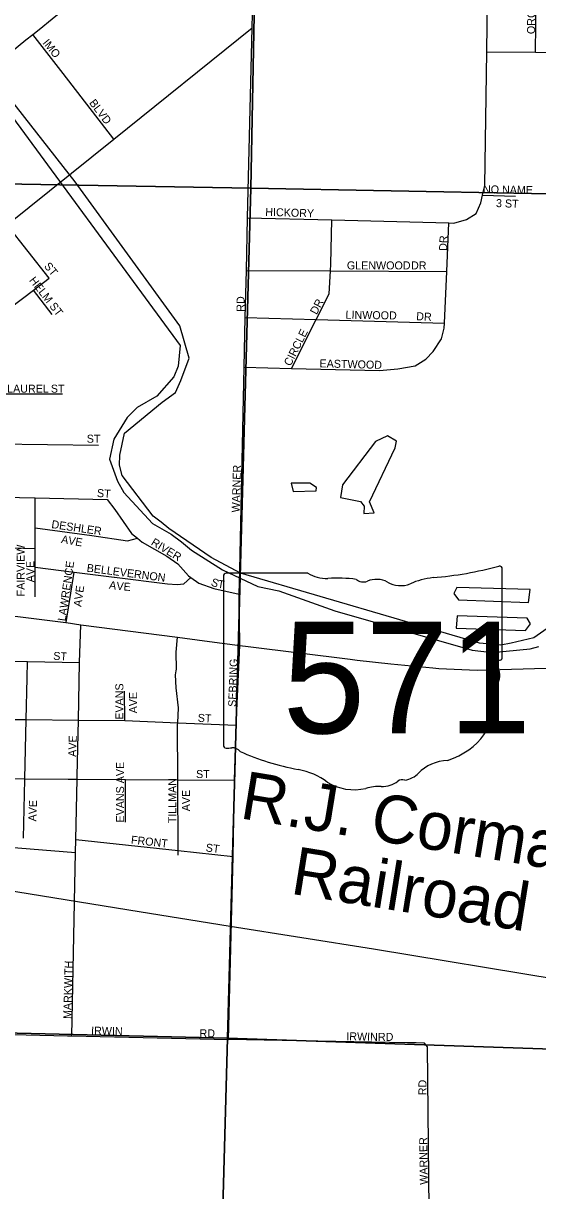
# Model space of a CAD drawing. Extents: x -784 to 1375, y -225 to 440.
# Drawn here: x 308.9 to 321.44, y 339.88 to 368.36 of the extents above; entities that cross this region are included whole.
import ezdxf

# ---------------------------------------------------------------- set-up
doc = ezdxf.new("R2010")
doc.units = 0
for name, color, linetype in [('GM_X_City_Street', 7, 'Continuous'), ('GM_X_City_Street_Text', 7, 'Continuous'), ('GM_X_County_Road', 7, 'Continuous'), ('GM_X_Major_River', 7, 'Continuous'), ('GM_X_Minor_Lake', 7, 'Continuous'), ('GM_X_Rail_Line', 7, 'Continuous'), ('GM_X_Rail_Line_Text', 7, 'Continuous'), ('GM_X_Section', 7, 'Continuous'), ('GM_X_State_Location', 7, 'Continuous'), ('GM_X_State_Route', 7, 'Continuous'), ('GM_X_State_Shield', 7, 'Continuous')]:
    doc.layers.add(name, color=color, linetype=linetype)

msp = doc.modelspace()

# ---------------------------------------------------------------- linework, layer by layer
at = {"layer": 'GM_X_City_Street'}
for points in [[(314.181, 355.025), (314.287, 359.97), (314.314, 361.184), (314.34, 362.327), (314.37, 363.611), (314.482, 368.251), (314.548, 370.985)], [(314.37, 363.611), (316.423, 363.56), (319.28, 363.488), (319.398, 363.485), (319.707, 363.569), (319.94, 363.718), (320.059, 363.98), (320.099, 364.162), (320.152, 364.4), (320.207, 367.666), (320.241, 370.994)], [(320.207, 367.666), (321.394, 367.658), (322.642, 367.65), (323.176, 367.646), (323.509, 367.729), (323.735, 367.91), (323.843, 368.102), (323.878, 370.999)], [(321.394, 367.658), (321.428, 370.996)], [(308.429, 363.378), (308.434, 363.382), (308.511, 363.444), (311.105, 365.533), (314.482, 368.251)], [(309.874, 367.13), (309.135, 368.088)], [(311.105, 365.533), (309.874, 367.13), (309.874, 367.13)], [(320.099, 364.162), (320.905, 364.14)], [(309.533, 362.144), (308.511, 363.444), (308.491, 363.47)], [(314.287, 359.97), (315.437, 359.941), (317.587, 359.885), (318.037, 359.933), (318.456, 360.006), (318.72, 360.162), (318.899, 360.351), (319.098, 360.658), (319.162, 360.923), (319.168, 361.04), (319.226, 362.307), (319.28, 363.488)], [(315.437, 359.941), (316.043, 361.133), (316.362, 361.76), (316.393, 362.319), (316.402, 362.479), (316.423, 363.56)], [(314.34, 362.327), (316.393, 362.319), (319.226, 362.307)], [(304.642, 358.327), (305.871, 359.317), (306.248, 359.621), (307.622, 360.677), (308.584, 361.415), (309.147, 361.848), (309.533, 362.144)], [(309.606, 361.257), (309.147, 361.848)], [(314.314, 361.184), (316.043, 361.133), (319.168, 361.04)], [(307.97, 359.317), (308.068, 359.317), (309.859, 359.316)], [(308.237, 358.1), (310.733, 358.066)], [(308.014, 356.811), (308.048, 356.81), (309.187, 356.785), (310.946, 356.745)], [(309.189, 355.978), (309.189, 356.048), (309.187, 356.785)], [(310.946, 356.745), (311.129, 356.498), (311.334, 356.203), (311.54, 355.916), (311.685, 355.796), (311.802, 355.699), (312.399, 355.356), (312.669, 355.17), (312.93, 354.882), (312.987, 354.842), (313.185, 354.704), (313.543, 354.57), (314.168, 354.429)], [(309.189, 356.048), (310.572, 355.86), (311.441, 355.731), (311.685, 355.796)], [(309.193, 354.364), (309.191, 355.093), (309.19, 355.548), (309.189, 355.978), (309.189, 355.978)], [(304.627, 355.657), (305.96, 355.625), (308.037, 355.576), (309.19, 355.548)], [(309.191, 355.093), (310.139, 354.972), (311.119, 354.847)], [(309.947, 353.744), (310.139, 354.972)], [(311.119, 354.847), (311.121, 354.847), (312.414, 354.682), (312.657, 354.669), (312.815, 354.681), (312.987, 354.842)], [(314.184, 353.183), (314.168, 354.429), (314.18, 355.007), (314.181, 355.025)], [(310.216, 350.004), (310.245, 351.361), (310.275, 352.764), (310.308, 353.688)], [(312.627, 352.565), (312.633, 352.6), (312.629, 353.017), (312.658, 353.382)], [(313.905, 343.57), (314.015, 348.032), (314.052, 349.896), (314.089, 351.235), (314.184, 353.183)], [(303.739, 352.922), (303.745, 352.922), (304.994, 352.879), (306.393, 352.848), (307.788, 352.818), (309.007, 352.792), (310.275, 352.764)], [(308.997, 352.381), (308.997, 352.381), (309.007, 352.792)], [(312.675, 348.066), (312.675, 348.178), (312.669, 349.906), (312.664, 351.26), (312.666, 351.296), (312.689, 351.659), (312.63, 352.146), (312.611, 352.463), (312.627, 352.565)], [(308.939, 349.914), (308.939, 349.914), (308.94, 349.93), (308.973, 351.371), (308.997, 352.381)], [(311.377, 351.351), (311.371, 352.065)], [(308.205, 351.378), (308.208, 351.378), (308.973, 351.371), (310.245, 351.361), (311.377, 351.351), (312.666, 351.296), (314.089, 351.235)], [(310.151, 346.933), (310.176, 348.128), (310.183, 348.449), (310.214, 349.922), (310.215, 349.948), (310.216, 350.004)], [(307.637, 349.939), (307.703, 349.939), (308.94, 349.93), (309.994, 349.923), (310.144, 349.922)], [(308.905, 348.476), (308.939, 349.914)], [(310.144, 349.922), (310.214, 349.922), (311.397, 349.914), (312.669, 349.906), (314.052, 349.896)], [(311.39, 348.868), (311.397, 349.914)], [(303.657, 348.589), (303.661, 348.589), (304.887, 348.56), (306.307, 348.444), (307.656, 348.334), (310.176, 348.128)], [(310.183, 348.449), (312.675, 348.178), (314.015, 348.032)], [(310.081, 343.658), (310.15, 346.904), (310.151, 346.933)], [(306.266, 343.745), (309.982, 343.66)], [(309.982, 343.66), (310.081, 343.658), (313.905, 343.57)], [(318.274, 343.489), (318.27, 343.489), (313.905, 343.57)], [(318.819, 336.84), (318.819, 336.84), (318.822, 337.048), (318.754, 343.386), (318.686, 343.482), (318.482, 343.485)]]:
    msp.add_lwpolyline(points, dxfattribs=at)
at = {"layer": 'GM_X_County_Road'}
msp.add_lwpolyline([(318.482, 343.485), (318.478, 343.485), (318.274, 343.489)], dxfattribs=at)
at = {"layer": 'GM_X_Major_River'}
for points in [[(321.839, 353.708), (321.346, 353.365), (320.794, 353.234), (320.542, 353.184), (320.024, 353.233), (314.199, 354.945), (313.484, 355.326), (312.452, 356.035), (312.259, 356.187), (312.065, 356.332), (311.314, 357.324), (311.248, 357.576), (311.253, 357.827), (311.365, 358.358), (312.29, 359.116), (312.616, 359.353), (312.74, 359.641), (312.946, 360.193), (312.717, 360.98), (310.168, 364.489), (307.645, 367.7), (307.182, 368.163), (306.803, 368.299)], [(308.16, 366.711), (312.724, 360.495), (312.675, 359.994), (312.568, 359.73), (312.159, 359.26), (311.675, 358.986), (311.435, 358.74), (311.111, 358.213), (311, 357.722), (311.202, 357.186), (311.354, 356.916), (312.054, 356.159), (312.505, 355.893), (312.76, 355.708), (313, 355.508), (313.761, 355.024), (314.617, 354.616), (315.133, 354.513), (316.498, 354.026), (319.848, 353.063), (320.342, 353.007), (321.262, 353.1), (321.475, 353.159)]]:
    msp.add_lwpolyline(points, dxfattribs=at)
at = {"layer": 'GM_X_Minor_Lake'}
for points in [[(318.004, 358.166), (317.779, 358.295), (317.486, 358.159), (316.681, 357.101), (316.636, 356.788)], [(316.636, 356.788), (317.121, 356.693), (317.213, 356.582), (317.202, 356.402), (317.453, 356.413), (317.34, 356.682), (317.97, 358.002), (318.004, 358.166)], [(315.889, 357.139), (315.433, 357.139), (315.484, 356.935), (316.042, 356.956)], [(316.042, 356.956), (316.051, 357.034), (315.889, 357.139)], [(321.258, 354.542), (319.469, 354.598), (319.395, 354.451), (319.51, 354.292)], [(319.51, 354.292), (321.221, 354.229), (321.258, 354.542)], [(321.19, 353.846), (319.479, 353.901), (319.458, 353.603)], [(319.458, 353.603), (321.145, 353.549), (321.266, 353.711), (321.19, 353.846)]]:
    msp.add_lwpolyline(points, dxfattribs=at)
at = {"layer": 'GM_X_Rail_Line'}
msp.add_lwpolyline([(303.626, 348.002), (306.309, 347.573), (311.473, 346.733), (313.943, 346.334), (317.442, 345.777), (321.968, 345.028), (324.501, 344.623), (326.856, 344.239), (328.997, 343.894), (333.611, 343.138)], dxfattribs=at)
at = {"layer": 'GM_X_Section'}
for points in [[(293.747, 385.447), (314.846, 385.028), (314.451, 364.338), (293.485, 364.699)], [(314.846, 385.028), (335.412, 384.667), (334.976, 363.947), (314.451, 364.338)], [(293.485, 364.699), (314.451, 364.338), (313.882, 343.598), (293.008, 344.097)], [(314.451, 364.338), (334.976, 363.947), (334.534, 342.899), (313.882, 343.598)], [(293.008, 344.097), (313.882, 343.598), (313.315, 322.896), (292.404, 323.388), (292.781, 344.102)], [(313.882, 343.598), (334.534, 342.899), (334.074, 322.46), (313.315, 322.896)]]:
    msp.add_lwpolyline(points, close=True, dxfattribs=at)
at = {"layer": 'GM_X_State_Route'}
for points in [[(309.286, 368.21), (309.607, 368.471), (310.402, 369.115)], [(308.967, 367.952), (309.135, 368.088), (309.285, 368.21), (309.286, 368.21)], [(308.329, 367.435), (308.777, 367.798), (308.966, 367.951), (308.967, 367.952)], [(306, 353.991), (306.535, 354.002), (307.588, 353.96), (307.797, 353.948), (308.024, 353.931), (308.77, 353.888), (309.936, 353.745), (309.947, 353.744), (310.308, 353.688), (312.658, 353.382), (313.321, 353.297), (314.184, 353.183), (314.388, 353.157)], [(314.388, 353.157), (316.874, 352.843), (317.045, 352.824)], [(317.045, 352.824), (317.864, 352.736), (318.89, 352.636)], [(318.89, 352.636), (319.037, 352.622), (319.968, 352.575), (321.923, 352.637), (322.974, 352.76), (324.625, 353.033), (324.827, 353.069)]]:
    msp.add_lwpolyline(points, dxfattribs=at)
at = {"layer": 'GM_X_State_Shield'}
for p, q in [((313.782, 354.875), (313.782, 350.748)), ((315.84, 354.946), (313.849, 354.946)), ((320.58, 352.889), (320.58, 355.048)), ((320.579, 352.89), (320.58, 352.889))]:
    msp.add_line(p, q, dxfattribs=at)
for centre, major_axis, start_param, end_param in [((318.159, 360.573), (7.209, 0), 4.814394, 5.042369), ((320.505, 355.057), (0.0757, 0), 6.141152, 7.989035), ((313.86, 354.884), (0.0788, 0), 1.712693, 3.28349), ((316.314, 355.425), (0.764, 0), 4.042523, 4.731795), ((316.567, 352.629), (2.742, 0), 1.404758, 1.657858), ((317.513, 354.428), (0.458, 0), 0.950623, 2.079405), ((319.078, 353.685), (1.45, 0), 1.699011, 2.107814), ((317.19, 354.905), (0.22, 0), 3.836095, 5.185415), ((318.105, 355.082), (0.551, 0), 4.081561, 5.145723), ((320.499, 352.881), (0.081, 0), 5.05454, 6.418171), ((320.563, 352.731), (0.117, 0), 1.883978, 3.671073), ((319.817, 352.458), (0.703, 0), 5.934695, 6.695948), ((320.851, 351.986), (0.511, 0), 2.387724, 3.262537), ((318.562, 351.711), (1.803, 0), 5.101752, 6.440018), ((313.861, 350.738), (0.0794, 0), 3.00124, 4.508301), ((313.873, 351.161), (0.606, 0), 4.665946, 4.897461), ((313.997, 350.509), (0.219, 0), 0.519207, 1.627899), ((316.757, 354.218), (5.206, 0), 4.195997, 4.488961), ((319.323, 349.589), (0.988, 0), 1.647645, 2.488434), ((315.205, 348.893), (1.629, 0), 0.823519, 1.323587), ((318.071, 350.347), (0.583, 0), 4.937069, 5.64225), ((316.967, 350.489), (1.034, 0), 4.026481, 4.996735), ((317.564, 349.062), (0.849, 0), 1.495662, 1.94098), ((317.639, 350.18), (0.551, 0), 4.691044, 5.507374), ((318.138, 349.78), (0.155, 0), 1.147584, 2.315152)]:
    msp.add_ellipse(centre, major_axis=major_axis, ratio=0.8, start_param=start_param, end_param=end_param, dxfattribs=at)

# ---------------------------------------------------------------- texts
at = {"layer": 'GM_X_City_Street_Text'}
for s, height, rotation, p in [('ORCHARD DR', 0.1953, 89.3707, (321.378, 368.094)), ('IMO', 0.1953, 308.9914, (309.361, 367.876)), ('BLVD', 0.1953, 307.4735, (310.496, 366.414)), ('NO NAME', 0.1953, 359.1053, (320.109, 364.212)), ('3 ST', 0.1953, 357.8801, (320.424, 363.876)), ('HICKORY', 0.1953, 358.1827, (314.799, 363.662)), ('DR', 0.1953, 86.9884, (319.23, 362.802)), ('ST', 0.1953, 309.8038, (309.395, 362.428)), ('GLENWOOD', 0.1953, 0, (316.791, 362.355)), ('DR', 0.1953, 0, (318.355, 362.355)), ('HELM ST', 0.1953, 308.0487, (309.034, 362.084)), ('RD', 0.1953, 90, (314.297, 361.322)), ('DR', 0.1953, 62.1061, (316.054, 361.236)), ('LINWOOD', 0.1953, 359.1324, (316.758, 361.152)), ('DR', 0.1953, 356.9889, (318.478, 361.118)), ('CIRCLE', 0.1953, 63.4339, (315.418, 359.98)), ('EASTWOOD', 0.1953, 358.532, (316.122, 359.966)), ('LAUREL', 0.1953, 0, (308.507, 359.348)), ('ST', 0.1953, 0, (309.573, 359.348)), ('ST', 0.1953, 0, (310.449, 358.127)), ('WARNER', 0.1953, 88.3627, (314.177, 356.424)), ('ST', 0.1953, 356.1881, (310.692, 356.804)), ('DESHLER', 0.1953, 351.7382, (309.578, 356.047)), ('AVE', 0.1953, 350.2226, (309.814, 355.682)), ('RIVER', 0.1953, 328.5727, (311.999, 355.646)), ('FAIRVIEW', 0.1953, 90, (308.934, 354.378)), ('AVE', 0.1953, 90, (309.167, 354.722)), ('LAWRENCE', 0.1953, 81.7639, (309.932, 353.765)), ('BELLEVERNON', 0.19531, 352.6654, (310.439, 354.981)), ('S', 0.195, 340.0659, (313.462, 354.649)), ('AVE', 0.1953, 82.1471, (310.316, 354.114)), ('A', 0.195, 351.135, (310.983, 354.568)), ('V', 0.195, 354.9053, (311.167, 354.54)), ('E', 0.195, 355.3948, (311.34, 354.524)), ('T', 0.195, 350.6844, (313.629, 354.592)), ('ST', 0.1953, 356.4256, (309.627, 352.833)), ('SEBRING', 0.1953, 88.0587, (314.091, 351.681)), ('EVANS', 0.1953, 90, (311.341, 351.37)), ('AVE', 0.1953, 90, (311.677, 351.525)), ('ST', 0.1953, 356.4256, (313.15, 351.321)), ('AVE', 0.1953, 88.0261, (310.189, 350.461)), ('EVANS AVE', 0.1953, 90, (311.358, 348.861)), ('ST', 0.1953, 0, (313.113, 349.946)), ('TILLMAN', 0.1953, 90, (312.63, 348.844)), ('AVE', 0.1953, 90, (312.966, 349.136)), ('AVE', 0.1953, 88.0242, (309.219, 348.885)), ('FRONT', 0.1953, 353.7953, (311.519, 348.347)), ('ST', 0.1953, 352.8653, (313.341, 348.158)), ('MARKWITH', 0.1953, 88.5313, (310.069, 344.067)), ('IRWIN', 0.1953, 358.6368, (310.553, 343.69)), ('RD', 0.1953, 0, (313.199, 343.621)), ('IRWIN', 0.1953, 358.6368, (316.775, 343.552)), ('RD', 0.1953, 0, (317.548, 343.535)), ('RD', 0.1953, 90, (318.731, 342.209)), ('WARNER', 0.1953, 90.818, (318.766, 340.026))]:
    msp.add_text(s, height=height, rotation=rotation, dxfattribs=at).set_placement(p)
at = {"layer": 'GM_X_Rail_Line_Text'}
for s, height, rotation, p in [('R.J. Corman', 1.16797, 350.7396, (314.155, 348.969)), ('Railroad', 1.168, 350.8563, (315.391, 347.129))]:
    msp.add_text(s, height=height, rotation=rotation, dxfattribs=at).set_placement(p)
at = {"layer": 'GM_X_State_Location'}
for s in ['s', 'r']:
    msp.add_text(s, height=0.00391, dxfattribs=at).set_placement((317.105, 352.537))
msp.add_text('571', height=0.00391, rotation=0, dxfattribs=at).set_placement((315.726, 352.253))
at = {"layer": 'GM_X_State_Shield'}
msp.add_text('571', height=2.7191, dxfattribs=at).set_placement((315.221, 351.039))

doc.saveas('drawing.dxf')
